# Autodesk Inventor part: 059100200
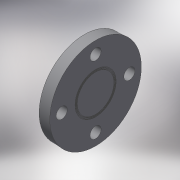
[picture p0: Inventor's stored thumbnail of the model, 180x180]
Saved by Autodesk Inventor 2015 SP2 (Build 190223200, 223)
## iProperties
Created: 2017-10
Part Number: 059100200
Material: Generic
Description: PLASSON BLANK FLANGE PVC 200
Document SubType Name: Modeling
Designer: KIM
Density: 1 g/cm^3
Appearance: Default
Author: KIM
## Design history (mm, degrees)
derived "059100.ipt"
feature "Solid1::059100.ipt"
tag "TaggingFeature1"
body "Solid1"
other parameters: "d0" = 32, "d3" = 336.6, "d12" = 45 deg, "d13" = 136, "d14" = 22, "d15" = 148.5, "d16" = 32, "d17" = 0, "d19" = 360 deg, "d21" = 1.7, "d22" = 1.7, "d23" = 1.7, "d24" = 1.7, "d25" = 1.7, "d26" = 0.68, "d27" = 0, "H_" = 32, "Dp_" = 297, "S_" = 22
